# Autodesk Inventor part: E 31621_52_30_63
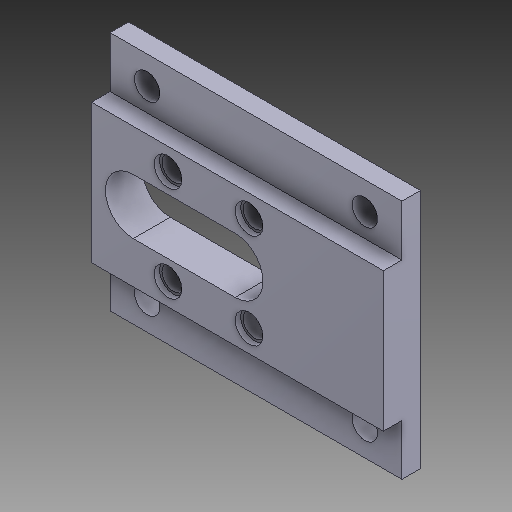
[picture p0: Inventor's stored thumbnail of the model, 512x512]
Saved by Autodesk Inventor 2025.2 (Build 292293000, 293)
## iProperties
Created: 2025-03
Part Number: E 31621_52_30_63
Material: Všeobecné
Document SubType Name: Modeling
Designer: Patrik
Density: 1 g/cm^3
Appearance: Výchozí
Mass: 16.5973 g
Surface Area: 85.6245 cm^2
Volume: 16.5973 cm^3
Author: Patrik
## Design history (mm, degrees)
feature "Base1"
node "Těleso1"
